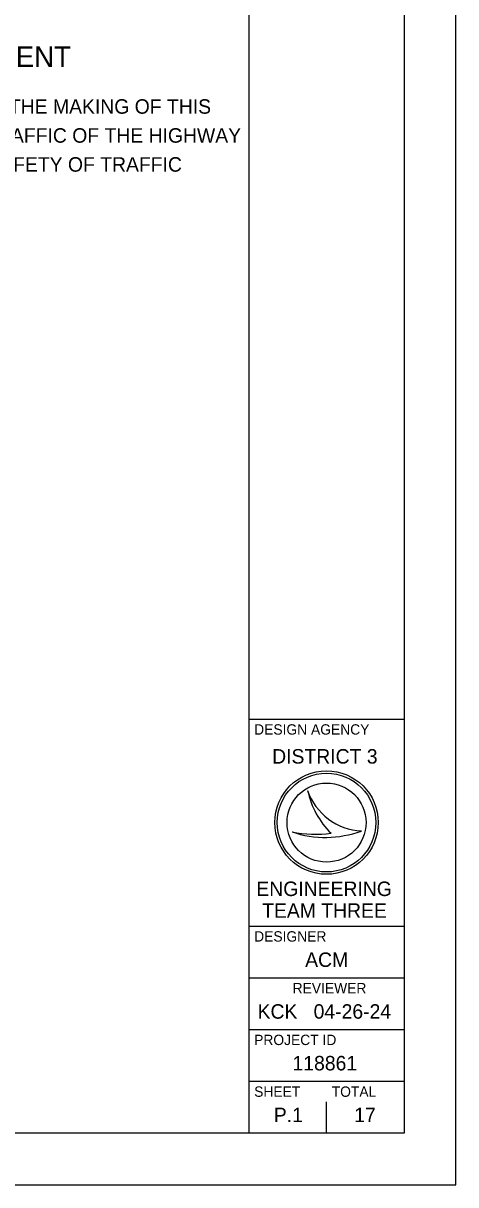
# Model space of a CAD drawing. Extents: x 0 to 34, y 0 to 22.
# Drawn here: x 29.82 to 34, y 0 to 11.22 of the extents above; entities that cross this region are included whole.
import ezdxf

# ---------------------------------------------------------------- set-up
doc = ezdxf.new("R2010")
doc.units = 0
for name, color, linetype in [('SH_Border', 7, 'Continuous'), ('SH_Cut_Line', 7, 'Continuous'), ('SH_Data', 7, 'Continuous'), ('SH_Text', 7, 'Continuous')]:
    doc.layers.add(name, color=color, linetype=linetype)

msp = doc.modelspace()

# ---------------------------------------------------------------- linework, layer by layer
at = {"layer": 'SH_Border'}
for p, q in [((32, 0.5), (32, 21.5)), ((32, 4.5), (33.5, 4.5)), ((32, 2.5), (33.5, 2.5)), ((32, 2), (33.5, 2)), ((32, 1.5), (33.5, 1.5)), ((32, 1), (33.5, 1))]:
    msp.add_line(p, q, dxfattribs=at)
msp.add_lwpolyline([(1.5, 21.5), (33.5, 21.5), (33.5, 0.5), (1.5, 0.5)], close=True, dxfattribs=at)
at = {"layer": 'SH_Cut_Line'}
msp.add_lwpolyline([(0, 0), (34, 0), (34, 22), (0, 22)], close=True, dxfattribs=at)
at = {"layer": 'SH_Data'}
for p, q in [((32.567, 3.81), (32.567, 3.81)), ((32.75, 3.5), (32.75, 3.5)), ((32.417, 3.41), (32.417, 3.41)), ((33.087, 3.419), (33.087, 3.419)), ((32.75, 0.5), (32.75, 0.8)), ((32.375, 0.675), (32.375, 0.675))]:
    msp.add_line(p, q, dxfattribs=at)
for radius in [0.5, 0.477, 0.477, 0.382]:
    msp.add_circle((32.75, 3.5), radius, dxfattribs=at)
for centre, radius, start, end in [((33.116, 3.998), 0.58, 198.9257, 198.9319), ((33.347, 3.97), 0.796, 191.6379, 191.6421), ((33.116, 3.998), 0.58, 198.9319, 267.1657), ((33.347, 3.97), 0.796, 191.6421, 226.0947), ((32.739, 4.37), 1.013, 251.4576, 290.0832), ((32.648, 4.654), 1.266, 259.4964, 259.4995), ((32.739, 4.37), 1.013, 251.4527, 251.4576), ((32.648, 4.654), 1.266, 259.4995, 276.6672)]:
    msp.add_arc(centre, radius, start, end, dxfattribs=at)

# ---------------------------------------------------------------- texts
for s, height, p in [('I HEREBY APPROVE THESE PLANS AND DECLARE THAT THE MAKING OF THIS', 0.14, (24.528, 10.35)), ('IMPROVEMENT WILL NOT REQUIRE THE CLOSING TO TRAFFIC OF THE HIGHWAY', 0.14, (24.528, 10.07)), ('AND THAT PROVISIONS FOR THE MAINTENANCE AND SAFETY OF TRAFFIC', 0.14, (24.528, 9.79)), ('DESIGN AGENCY', 0.1, (32.05, 4.35)), ('DISTRICT 3', 0.14, (32.224, 4.07)), ('ENGINEERING', 0.14, (32.071, 2.79)), ('TEAM THREE', 0.14, (32.127, 2.58)), ('DESIGNER', 0.1, (32.05, 2.35)), ('ACM', 0.14, (32.543, 2.105)), ('REVIEWER', 0.1, (32.422, 1.85)), ('KCK', 0.14, (32.083, 1.605)), ('04-26-24', 0.14, (32.625, 1.605)), ('PROJECT ID', 0.1, (32.05, 1.35)), ('118861', 0.14, (32.421, 1.105)), ('SHEET', 0.1, (32.05, 0.85)), ('TOTAL', 0.1, (32.8, 0.85)), ('P.1', 0.14, (32.24, 0.605)), ('17', 0.14, (33.018, 0.605))]:
    msp.add_text(s, height=height, dxfattribs=at).set_placement(p)
at = {"layer": 'SH_Text'}
msp.add_text('MAINTENANCE OF TRAFFIC ENDORSEMENT', height=0.2, dxfattribs=at).set_placement((24.528, 10.802))

doc.saveas('drawing.dxf')
